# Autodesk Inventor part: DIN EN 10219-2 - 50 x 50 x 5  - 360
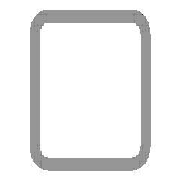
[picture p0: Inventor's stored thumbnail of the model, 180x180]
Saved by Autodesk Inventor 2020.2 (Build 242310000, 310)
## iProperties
Created: 2019-10
Part Number: DIN EN 10219-2 - 50 x 50 x 5  - 360
Material: Stahl, weich
Description: Kaltgeformte, geschweißte Baustahl-Hohlprofile aus unlegiertem Feinkorn-Baustahl
Document SubType Name: Modeling
Standard: DIN
Designer: lutzd
Standard Revision: 2006-07
Standards Organization: DIN
Language: de-DE
Size Designation: 50 x 50 x 5
Categories: <MemberInstance><Categories><Category DisplayName="Profile" InternalName="089c4875-fa83-4c05-b084-43b9cc11f5ed" Mnemonic="GRDR"><CategoryParameter DisplayName="
Stock Number: 50 x 50 x 5
Mass: 2358.74 g
Surface Area: 1220.7 cm^2
Volume: 300.476 cm^3
Density: 7.85 g/cm^3
Appearance: Semi-Polished(8)
IsCustomPart: 1
G_L: 360,000 mm
G_W: 50,000 mm
G_H: 50,000 mm
Mass: 2,359 kg
VLT_Material: Stahl, weich
DocNumber: ADSK-014378
Folder: .
+00266F1F-5B55-4877-92D0-0DD50DE4C5F7+SCHNITTDETAIL1: Schnittwinkel 90,00 grd
Dimensions: 50x50x360 mm
_CCFamilyMember: 16
_CCFamilyDisplayName: DIN EN 10219-2 (Quadratisches Hohlprofil - Kaltgeformt) - Kaltgeformte, geschweißte Baustahl-Hohlprofile aus unlegiertem Feinkorn-Baustahl
_FrameMemberDoc: Frame Member File
_Version: 15.0.0
_GetPNFromCC: 1
Title: Profil-Bauteil
Author: lutzd
Revision Number: -
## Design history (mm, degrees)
node "Startebene"
node "Endebene"
sketch "Skizze"
  geometry: L1 (-25, -15)-(-25, 15); L2 (-15, 25)-(15, 25); L3 (25, 15)-(25, -15); L4 (15, -25)-(-15, -25); L5 (-15, 20)-(15, 20); L6 (20, 15)-(20, -15); L7 (15, -20)-(-15, -20); L8 (-20, -15)-(-20, 15); L9 (0, 37.899)-(0, -37.899) reference; L10 (-37.899, 0)-(37.899, 0) reference; A1 r 10 centre (-15, -15) between (-25, -15) and (-15, -25); A2 r 10 centre (-15, 15) between (-15, 25) and (-25, 15); A3 r 10 centre (15, 15) between (25, 15) and (15, 25); A4 r 10 centre (15, -15) between (15, -25) and (25, -15); A5 r 5 centre (-15, 15) between (-15, 20) and (-20, 15); A6 r 5 centre (15, 15) between (20, 15) and (15, 20); A7 r 5 centre (15, -15) between (15, -20) and (20, -15); A8 r 5 centre (-15, -15) between (-20, -15) and (-15, -20)
  constraints: 16 end point, 16 point on circle, 8 centre point, 8 tangent, 4 parallel, 3 equal radius, 2 perpendicular, 7 other
  dimensions: "d7" = 10 radius of A1 (= G_IR); "d10" = 50 distance between parallel lines of L2 L4 (= G_H); "d11" = 50 distance between parallel lines of L1 L3 (= G_W); "d12" = 5 distance between parallel lines of L3 L6 (= G_T); "d15" = 25 distance between parallel lines of L2 L10 (= 0.5 x d10); "d16" = 25 distance between parallel lines of L9 L3 (= 0.5 x d11)
extrude "Körper" new body sketch "Skizze" stored distance "d3" = 360 (= G_L); taper "d4" = 0 deg
node "Driven Length"
  sketch "Sketch3"
    geometry: L1 (0, 0)-(10, 0) reference
    constraints: 2 end point, 1 horizontal
  workplane "Work Plane3"
  sketch "Sketch4"
    geometry: L1 (-2, 50)-(12, 50) reference; L2 (-2, 410)-(12, 410) reference
    dimensions: "d18" = 360 distance between parallel lines of L1 L2 (derived)
workplane "Arbeitsebene4"
feature "Trennen1"
sketch "Skizze5"
  geometry: L1 (-30, 360)-(0, 360) reference; L2 (-15, 360)-(-15, 31); 3 further points
  constraints: 2 end point, 1 coincident, 1 midpoint, 1 point on line, 1 vertical
  dimensions: "d19" = 254 distance of point (-15, 31) point (-15, 285); "d20" = 75 distance from line of point (-15, 285) L1
hole "Bohrung1" sketch "Skizze5" at (-15, 31), (-15, 285) diameter "d21" = 6.647; stored, may be unused: countersink angle "d25" = 90 deg, drill point angle "d27" = 118 deg; dims "d22" = 16, "d23" = 4, "d24" = 2, "d26" = 8
body "Solid1"
other parameters: "G_W" = 50 [user parameter; used in 1 equation term], "G_H" = 50 [user parameter; used in 1 equation term], "G_T" = 5 [user parameter; used in 1 equation term], "G_IR" = 10 [user parameter; used in 1 equation term], "G_L" = 360 (= d18) [user parameter; used in 1 equation term], "G_OFFSET_END" = 0 [user parameter; used in 1 equation term], "d17" = 90 deg
